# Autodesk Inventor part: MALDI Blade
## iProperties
Shininess: 64.0
Length Units: 11272
Angle Units: 11279
Time Units: 11290
Mass Units: 11286
Length Display Precision: 4
Angle Display Precision: 2
Compacted: True
Part Number: MALDI Blade
Document SubType Name: Modeling
Created: 2003-08
Designer: jpittman
Manufacturer: Standard
Standards Organization: Custom
Density: 0.0
Volumn: 0.0
Area: 0.0
PropertySet Name: Model Information
Control State: 0
Master: False
Checked Out: False
Author: jpittman
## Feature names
1. Blade Body [Extrusion]
2. Fillet2
3. Extrusion3
4. Hole3
5. Hole4
6. Extrusion6
7. Hole8
8. Extrusion7
9. Fillet6
